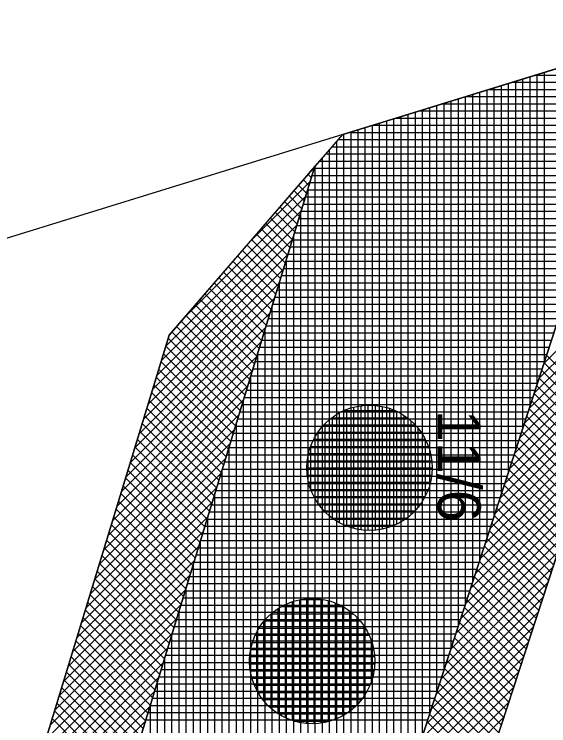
# Model space of a CAD drawing. Extents: x -565346 to -564154, y -1097386 to -1095620.
# Drawn here: x -564238.99 to -564224.07, y -1096458.56 to -1096438.69 of the extents above; entities that cross this region are included whole.
import ezdxf

# ---------------------------------------------------------------- set-up
doc = ezdxf.new("R2010")
doc.units = 0
for name, color, linetype in [('Vrstva 1', 7, 'Continuous'), ('Vrstva 13', 7, 'Continuous'), ('Vrstva 40', 7, 'Continuous'), ('Vrstva 41', 7, 'Continuous'), ('Vrstva 42', 7, 'Continuous'), ('Vrstva 43', 7, 'Continuous'), ('Vrstva 44', 7, 'Continuous')]:
    doc.layers.add(name, color=color, linetype=linetype)

msp = doc.modelspace()

# ---------------------------------------------------------------- linework, layer by layer
at = {"layer": 'Vrstva 1'}
for p, q in [((-564229.82, -1096442.05), (-564218.92, -1096438.69)), ((-564229.82, -1096442.05), (-564251.25, -1096448.66)), ((-564234.67, -1096447.65), (-564229.82, -1096442.05)), ((-564259.14, -1096527.84), (-564234.67, -1096447.65))]:
    msp.add_line(p, q, dxfattribs=at)
at = {"layer": 'Vrstva 13'}
msp.add_line((-564218.92, -1096438.69), (-564226.29, -1096461.3), dxfattribs=at)
at = {"layer": 'Vrstva 41'}
for points in [[(-564230.6, -1096442.93), (-564234.67, -1096447.65), (-564259.14, -1096527.84), (-564264.72, -1096575.85), (-564272.07, -1096706.16), (-564269.623, -1096706.334), (-564262.228, -1096576.061), (-564256.683, -1096528.354)], [(-564221.399, -1096446.296), (-564223.301, -1096445.676), (-564228.215, -1096460.758), (-564240.675, -1096505.018), (-564249.271, -1096529.938), (-564254.757, -1096576.767), (-564262.137, -1096706.758), (-564260.141, -1096706.872), (-564252.76, -1096576.88), (-564247.38, -1096530.59), (-564238.75, -1096505.56), (-564226.29, -1096461.3)]]:
    msp.add_lwpolyline(points, close=True, dxfattribs=at)
at = {"layer": 'Vrstva 42'}
for p, q in [((-564230.608, -1096442.955), (-564230.71, -1096443.057)), ((-564230.664, -1096443.004), (-564230.632, -1096443.036)), ((-564230.926, -1096443.308), (-564230.765, -1096443.469)), ((-564230.795, -1096443.156), (-564230.699, -1096443.253)), ((-564230.732, -1096443.362), (-564232.481, -1096445.111)), ((-564231.057, -1096443.46), (-564230.831, -1096443.686)), ((-564231.188, -1096443.612), (-564230.897, -1096443.903)), ((-564230.856, -1096443.77), (-564234.252, -1096447.165)), ((-564231.45, -1096443.916), (-564231.029, -1096444.336)), ((-564231.319, -1096443.764), (-564230.963, -1096444.12)), ((-564231.581, -1096444.068), (-564231.096, -1096444.553)), ((-564230.981, -1096444.177), (-564234.765, -1096447.961)), ((-564231.712, -1096444.219), (-564231.162, -1096444.77)), ((-564231.843, -1096444.371), (-564231.228, -1096444.986)), ((-564231.105, -1096444.584), (-564234.889, -1096448.368)), ((-564232.105, -1096444.675), (-564231.36, -1096445.42)), ((-564231.974, -1096444.523), (-564231.294, -1096445.203)), ((-564232.236, -1096444.827), (-564231.426, -1096445.636)), ((-564231.229, -1096444.991), (-564235.013, -1096448.775)), ((-564232.367, -1096444.979), (-564231.492, -1096445.853)), ((-564232.629, -1096445.283), (-564231.625, -1096446.286)), ((-564232.498, -1096445.131), (-564231.559, -1096446.07)), ((-564231.354, -1096445.398), (-564235.138, -1096449.182)), ((-564232.76, -1096445.434), (-564231.691, -1096446.503)), ((-564232.891, -1096445.586), (-564231.757, -1096446.72)), ((-564231.478, -1096445.805), (-564235.262, -1096449.589)), ((-564233.152, -1096445.89), (-564231.889, -1096447.153)), ((-564233.021, -1096445.738), (-564231.823, -1096446.936)), ((-564233.283, -1096446.042), (-564231.956, -1096447.37)), ((-564231.602, -1096446.213), (-564235.386, -1096449.996)), ((-564233.414, -1096446.194), (-564232.022, -1096447.586)), ((-564221.471, -1096446.273), (-564224.474, -1096449.275)), ((-564221.685, -1096446.203), (-564224.337, -1096448.855)), ((-564221.898, -1096446.134), (-564224.2, -1096448.436)), ((-564233.676, -1096446.498), (-564232.154, -1096448.02)), ((-564233.545, -1096446.346), (-564232.088, -1096447.803)), ((-564231.727, -1096446.62), (-564235.51, -1096450.403)), ((-564233.807, -1096446.649), (-564232.22, -1096448.236)), ((-564221.49, -1096446.574), (-564224.61, -1096449.694)), ((-564233.938, -1096446.801), (-564232.286, -1096448.453)), ((-564231.851, -1096447.027), (-564235.634, -1096450.81)), ((-564234.069, -1096446.953), (-564232.353, -1096448.67)), ((-564221.627, -1096446.994), (-564224.747, -1096450.114)), ((-564234.331, -1096447.257), (-564232.485, -1096449.103)), ((-564234.2, -1096447.105), (-564232.419, -1096448.887)), ((-564231.975, -1096447.434), (-564235.759, -1096451.217)), ((-564234.462, -1096447.409), (-564232.551, -1096449.32)), ((-564221.763, -1096447.413), (-564224.884, -1096450.533)), ((-564234.593, -1096447.561), (-564232.617, -1096449.537)), ((-564232.1, -1096447.841), (-564235.883, -1096451.624)), ((-564234.697, -1096447.739), (-564232.683, -1096449.753)), ((-564221.9, -1096447.833), (-564225.02, -1096450.953)), ((-564234.763, -1096447.956), (-564232.75, -1096449.97)), ((-564232.224, -1096448.248), (-564236.007, -1096452.031)), ((-564234.83, -1096448.173), (-564232.816, -1096450.187)), ((-564222.037, -1096448.252), (-564225.157, -1096451.372)), ((-564224.127, -1096448.213), (-564222.541, -1096449.799)), ((-564234.896, -1096448.389), (-564232.882, -1096450.403)), ((-564224.197, -1096448.426), (-564222.611, -1096450.012)), ((-564232.348, -1096448.656), (-564236.131, -1096452.439)), ((-564234.962, -1096448.606), (-564232.948, -1096450.62)), ((-564222.174, -1096448.672), (-564225.294, -1096451.792)), ((-564224.266, -1096448.639), (-564222.68, -1096450.226)), ((-564235.028, -1096448.823), (-564233.014, -1096450.837)), ((-564224.336, -1096448.853), (-564222.75, -1096450.439)), ((-564232.473, -1096449.063), (-564236.255, -1096452.846)), ((-564235.094, -1096449.04), (-564233.08, -1096451.053)), ((-564224.405, -1096449.066), (-564222.819, -1096450.652)), ((-564235.16, -1096449.256), (-564233.147, -1096451.27)), ((-564222.311, -1096449.092), (-564225.43, -1096452.211)), ((-564224.475, -1096449.279), (-564222.889, -1096450.865)), ((-564232.597, -1096449.47), (-564236.38, -1096453.253)), ((-564235.226, -1096449.473), (-564233.213, -1096451.487)), ((-564222.447, -1096449.511), (-564225.567, -1096452.631)), ((-564224.544, -1096449.493), (-564222.958, -1096451.079)), ((-564232.721, -1096449.877), (-564236.504, -1096453.66)), ((-564235.292, -1096449.69), (-564233.279, -1096451.703)), ((-564224.614, -1096449.706), (-564223.028, -1096451.292)), ((-564235.359, -1096449.906), (-564233.345, -1096451.92)), ((-564222.584, -1096449.931), (-564225.704, -1096453.051)), ((-564224.684, -1096449.919), (-564223.097, -1096451.505)), ((-564235.425, -1096450.123), (-564233.411, -1096452.137)), ((-564224.753, -1096450.133), (-564223.167, -1096451.719)), ((-564232.845, -1096450.284), (-564236.628, -1096454.067)), ((-564235.491, -1096450.34), (-564233.477, -1096452.353)), ((-564222.721, -1096450.351), (-564225.84, -1096453.47)), ((-564224.823, -1096450.346), (-564223.236, -1096451.932)), ((-564235.557, -1096450.557), (-564233.543, -1096452.57)), ((-564224.892, -1096450.559), (-564223.306, -1096452.145)), ((-564232.97, -1096450.691), (-564236.752, -1096454.474)), ((-564235.623, -1096450.773), (-564233.61, -1096452.787)), ((-564222.858, -1096450.77), (-564225.977, -1096453.89)), ((-564224.962, -1096450.773), (-564223.375, -1096452.359)), ((-564235.689, -1096450.99), (-564233.676, -1096453.003)), ((-564225.031, -1096450.986), (-564223.445, -1096452.572)), ((-564233.094, -1096451.098), (-564236.876, -1096454.881)), ((-564235.755, -1096451.207), (-564233.742, -1096453.22)), ((-564222.994, -1096451.19), (-564226.114, -1096454.309)), ((-564225.101, -1096451.199), (-564223.515, -1096452.785)), ((-564235.821, -1096451.423), (-564233.808, -1096453.437)), ((-564225.17, -1096451.413), (-564223.584, -1096452.999)), ((-564233.218, -1096451.506), (-564237.001, -1096455.288)), ((-564235.888, -1096451.64), (-564233.874, -1096453.654)), ((-564223.131, -1096451.609), (-564226.251, -1096454.729)), ((-564225.24, -1096451.626), (-564223.654, -1096453.212)), ((-564235.954, -1096451.857), (-564233.94, -1096453.87)), ((-564225.309, -1096451.839), (-564223.723, -1096453.425)), ((-564233.343, -1096451.913), (-564237.125, -1096455.695)), ((-564223.268, -1096452.029), (-564226.387, -1096455.148)), ((-564225.379, -1096452.053), (-564223.793, -1096453.638)), ((-564236.02, -1096452.074), (-564234.007, -1096454.087)), ((-564233.467, -1096452.32), (-564237.249, -1096456.102)), ((-564236.086, -1096452.29), (-564234.073, -1096454.304)), ((-564223.405, -1096452.449), (-564226.524, -1096455.568)), ((-564225.448, -1096452.266), (-564223.862, -1096453.852)), ((-564236.152, -1096452.507), (-564234.139, -1096454.52)), ((-564225.518, -1096452.479), (-564223.932, -1096454.065)), ((-564233.591, -1096452.727), (-564237.373, -1096456.509)), ((-564236.218, -1096452.724), (-564234.205, -1096454.737)), ((-564225.587, -1096452.693), (-564224.001, -1096454.278)), ((-564236.284, -1096452.94), (-564234.271, -1096454.954)), ((-564223.542, -1096452.868), (-564226.661, -1096455.987)), ((-564225.657, -1096452.906), (-564224.071, -1096454.492)), ((-564233.716, -1096453.134), (-564237.498, -1096456.916)), ((-564236.351, -1096453.157), (-564234.337, -1096455.17)), ((-564225.726, -1096453.119), (-564224.14, -1096454.705)), ((-564236.417, -1096453.374), (-564234.404, -1096455.387)), ((-564223.678, -1096453.288), (-564226.797, -1096456.407)), ((-564225.796, -1096453.333), (-564224.21, -1096454.918)), ((-564233.84, -1096453.541), (-564237.622, -1096457.323)), ((-564236.483, -1096453.591), (-564234.47, -1096455.604)), ((-564225.865, -1096453.546), (-564224.279, -1096455.132)), ((-564236.549, -1096453.807), (-564234.536, -1096455.82)), ((-564223.815, -1096453.708), (-564226.934, -1096456.826)), ((-564225.935, -1096453.759), (-564224.349, -1096455.345)), ((-564233.964, -1096453.949), (-564237.746, -1096457.73)), ((-564236.615, -1096454.024), (-564234.602, -1096456.037)), ((-564226.004, -1096453.973), (-564224.418, -1096455.558)), ((-564236.681, -1096454.241), (-564234.668, -1096456.254)), ((-564223.952, -1096454.127), (-564227.071, -1096457.246)), ((-564226.074, -1096454.186), (-564224.488, -1096455.772)), ((-564234.089, -1096454.356), (-564237.87, -1096458.137)), ((-564226.143, -1096454.399), (-564224.557, -1096455.985)), ((-564236.747, -1096454.457), (-564234.734, -1096456.47)), ((-564224.089, -1096454.547), (-564227.207, -1096457.665)), ((-564226.213, -1096454.613), (-564224.627, -1096456.198)), ((-564234.213, -1096454.763), (-564237.994, -1096458.544)), ((-564236.813, -1096454.674), (-564234.801, -1096456.687)), ((-564226.282, -1096454.826), (-564224.697, -1096456.412)), ((-564236.88, -1096454.891), (-564234.867, -1096456.904)), ((-564224.225, -1096454.966), (-564227.344, -1096458.085)), ((-564226.352, -1096455.039), (-564224.766, -1096456.625)), ((-564234.337, -1096455.17), (-564238.119, -1096458.951)), ((-564236.946, -1096455.108), (-564234.933, -1096457.12)), ((-564237.012, -1096455.324), (-564234.999, -1096457.337)), ((-564224.362, -1096455.386), (-564227.481, -1096458.505)), ((-564226.421, -1096455.253), (-564224.836, -1096456.838)), ((-564234.462, -1096455.577), (-564238.243, -1096459.358)), ((-564237.078, -1096455.541), (-564235.065, -1096457.554)), ((-564226.491, -1096455.466), (-564224.905, -1096457.051)), ((-564237.144, -1096455.758), (-564235.131, -1096457.77)), ((-564224.499, -1096455.806), (-564227.617, -1096458.924)), ((-564226.56, -1096455.679), (-564224.975, -1096457.265)), ((-564234.586, -1096455.984), (-564238.367, -1096459.766)), ((-564237.21, -1096455.974), (-564235.197, -1096457.987)), ((-564226.63, -1096455.893), (-564225.044, -1096457.478)), ((-564237.276, -1096456.191), (-564235.264, -1096458.204)), ((-564224.636, -1096456.225), (-564227.754, -1096459.344)), ((-564226.699, -1096456.106), (-564225.114, -1096457.691)), ((-564234.71, -1096456.392), (-564238.491, -1096460.173)), ((-564237.342, -1096456.408), (-564235.33, -1096458.421)), ((-564226.769, -1096456.319), (-564225.183, -1096457.905)), ((-564237.409, -1096456.625), (-564235.396, -1096458.637)), ((-564226.838, -1096456.533), (-564225.253, -1096458.118)), ((-564234.835, -1096456.799), (-564238.615, -1096460.58)), ((-564224.773, -1096456.645), (-564227.891, -1096459.763)), ((-564226.908, -1096456.746), (-564225.322, -1096458.331)), ((-564237.475, -1096456.841), (-564235.462, -1096458.854)), ((-564226.977, -1096456.959), (-564225.392, -1096458.545)), ((-564234.959, -1096457.206), (-564238.74, -1096460.987)), ((-564237.541, -1096457.058), (-564235.528, -1096459.071)), ((-564224.909, -1096457.065), (-564228.028, -1096460.183)), ((-564227.047, -1096457.173), (-564225.461, -1096458.758)), ((-564237.607, -1096457.275), (-564235.594, -1096459.287)), ((-564227.116, -1096457.386), (-564225.531, -1096458.971)), ((-564235.083, -1096457.613), (-564238.864, -1096461.394)), ((-564237.673, -1096457.491), (-564235.661, -1096459.504)), ((-564225.046, -1096457.484), (-564228.164, -1096460.602)), ((-564227.186, -1096457.599), (-564225.6, -1096459.185)), ((-564237.739, -1096457.708), (-564235.727, -1096459.721)), ((-564227.255, -1096457.813), (-564225.67, -1096459.398)), ((-564235.208, -1096458.02), (-564238.988, -1096461.801)), ((-564237.805, -1096457.925), (-564235.793, -1096459.937)), ((-564225.183, -1096457.904), (-564228.285, -1096461.005)), ((-564227.325, -1096458.026), (-564225.74, -1096459.611)), ((-564237.872, -1096458.142), (-564235.859, -1096460.154)), ((-564237.938, -1096458.358), (-564235.925, -1096460.371)), ((-564225.32, -1096458.323), (-564228.395, -1096461.399)), ((-564227.394, -1096458.239), (-564225.809, -1096459.825)), ((-564235.332, -1096458.427), (-564239.112, -1096462.208)), ((-564227.464, -1096458.453), (-564225.879, -1096460.038))]:
    msp.add_line(p, q, dxfattribs=at)
at = {"layer": 'Vrstva 43'}
for p, q in [((-564224.19, -1096448.405), (-564224.19, -1096440.315)), ((-564224.79, -1096450.246), (-564224.79, -1096440.499)), ((-564224.59, -1096449.632), (-564224.59, -1096440.438)), ((-564224.435, -1096440.39), (-564219.474, -1096440.39)), ((-564224.39, -1096449.018), (-564224.39, -1096440.376)), ((-564225.39, -1096452.088), (-564225.39, -1096440.684)), ((-564225.19, -1096451.474), (-564225.19, -1096440.623)), ((-564225.084, -1096440.59), (-564219.539, -1096440.59)), ((-564224.99, -1096450.86), (-564224.99, -1096440.561)), ((-564226.19, -1096454.543), (-564226.19, -1096440.931)), ((-564225.99, -1096453.929), (-564225.99, -1096440.869)), ((-564225.79, -1096453.315), (-564225.79, -1096440.808)), ((-564225.732, -1096440.79), (-564219.605, -1096440.79)), ((-564225.59, -1096452.701), (-564225.59, -1096440.746)), ((-564226.79, -1096456.384), (-564226.79, -1096441.116)), ((-564226.59, -1096455.771), (-564226.59, -1096441.054)), ((-564226.39, -1096455.157), (-564226.39, -1096440.993)), ((-564226.381, -1096440.99), (-564219.67, -1096440.99)), ((-564227.39, -1096458.226), (-564227.39, -1096441.301)), ((-564227.19, -1096457.612), (-564227.19, -1096441.239)), ((-564227.03, -1096441.19), (-564219.735, -1096441.19)), ((-564226.99, -1096456.998), (-564226.99, -1096441.178)), ((-564227.99, -1096460.067), (-564227.99, -1096441.486)), ((-564227.79, -1096459.454), (-564227.79, -1096441.424)), ((-564227.679, -1096441.39), (-564219.8, -1096441.39)), ((-564227.59, -1096458.84), (-564227.59, -1096441.363)), ((-564228.79, -1096462.801), (-564228.79, -1096441.732)), ((-564228.59, -1096462.09), (-564228.59, -1096441.671)), ((-564228.39, -1096461.38), (-564228.39, -1096441.609)), ((-564228.328, -1096441.59), (-564219.865, -1096441.59)), ((-564228.19, -1096460.681), (-564228.19, -1096441.548)), ((-564229.39, -1096464.932), (-564229.39, -1096441.917)), ((-564229.19, -1096464.221), (-564229.19, -1096441.856)), ((-564228.99, -1096463.511), (-564228.99, -1096441.794)), ((-564228.977, -1096441.79), (-564219.93, -1096441.79)), ((-564229.79, -1096466.353), (-564229.79, -1096442.041)), ((-564229.625, -1096441.99), (-564219.996, -1096441.99)), ((-564229.59, -1096465.642), (-564229.59, -1096441.979)), ((-564229.99, -1096467.063), (-564229.99, -1096442.242)), ((-564229.944, -1096442.19), (-564220.061, -1096442.19)), ((-564230.19, -1096467.774), (-564230.19, -1096442.467)), ((-564230.121, -1096442.39), (-564220.126, -1096442.39)), ((-564230.39, -1096468.484), (-564230.39, -1096442.693)), ((-564230.299, -1096442.59), (-564220.191, -1096442.59)), ((-564230.59, -1096469.194), (-564230.59, -1096442.919)), ((-564230.476, -1096442.79), (-564220.256, -1096442.79)), ((-564230.618, -1096442.99), (-564220.322, -1096442.99)), ((-564230.679, -1096443.19), (-564220.387, -1096443.19)), ((-564230.74, -1096443.39), (-564220.452, -1096443.39)), ((-564230.802, -1096443.59), (-564220.517, -1096443.59)), ((-564230.79, -1096469.905), (-564230.79, -1096443.552)), ((-564230.863, -1096443.79), (-564220.582, -1096443.79)), ((-564230.924, -1096443.99), (-564220.648, -1096443.99)), ((-564230.99, -1096470.615), (-564230.99, -1096444.207)), ((-564230.985, -1096444.19), (-564220.713, -1096444.19)), ((-564231.046, -1096444.39), (-564220.778, -1096444.39)), ((-564231.107, -1096444.59), (-564220.843, -1096444.59)), ((-564231.19, -1096471.326), (-564231.19, -1096444.862)), ((-564231.168, -1096444.79), (-564220.908, -1096444.79)), ((-564231.229, -1096444.99), (-564220.974, -1096444.99)), ((-564231.29, -1096445.19), (-564221.039, -1096445.19)), ((-564231.351, -1096445.39), (-564221.104, -1096445.39)), ((-564231.412, -1096445.59), (-564221.169, -1096445.59)), ((-564231.39, -1096472.036), (-564231.39, -1096445.517)), ((-564231.473, -1096445.79), (-564223.338, -1096445.79)), ((-564231.534, -1096445.99), (-564223.403, -1096445.99)), ((-564231.595, -1096446.19), (-564223.468, -1096446.19)), ((-564231.59, -1096472.747), (-564231.59, -1096446.172)), ((-564231.656, -1096446.39), (-564223.534, -1096446.39)), ((-564231.718, -1096446.59), (-564223.599, -1096446.59)), ((-564231.79, -1096473.457), (-564231.79, -1096446.827)), ((-564231.779, -1096446.79), (-564223.664, -1096446.79)), ((-564231.84, -1096446.99), (-564223.729, -1096446.99)), ((-564231.901, -1096447.19), (-564223.794, -1096447.19)), ((-564231.99, -1096474.167), (-564231.99, -1096447.482)), ((-564231.962, -1096447.39), (-564223.859, -1096447.39)), ((-564232.023, -1096447.59), (-564223.925, -1096447.59)), ((-564232.084, -1096447.79), (-564223.99, -1096447.79)), ((-564232.145, -1096447.99), (-564224.055, -1096447.99)), ((-564232.206, -1096448.19), (-564224.12, -1096448.19)), ((-564232.19, -1096474.878), (-564232.19, -1096448.137)), ((-564232.267, -1096448.39), (-564224.185, -1096448.39)), ((-564232.328, -1096448.59), (-564224.25, -1096448.59)), ((-564232.39, -1096475.588), (-564232.39, -1096448.792)), ((-564232.389, -1096448.79), (-564224.316, -1096448.79)), ((-564232.45, -1096448.99), (-564224.381, -1096448.99)), ((-564232.511, -1096449.19), (-564224.446, -1096449.19)), ((-564232.59, -1096476.299), (-564232.59, -1096449.447)), ((-564232.572, -1096449.39), (-564224.511, -1096449.39)), ((-564232.634, -1096449.59), (-564224.576, -1096449.59)), ((-564232.695, -1096449.79), (-564224.641, -1096449.79)), ((-564232.756, -1096449.99), (-564224.707, -1096449.99)), ((-564232.817, -1096450.19), (-564224.772, -1096450.19)), ((-564232.79, -1096477.009), (-564232.79, -1096450.102)), ((-564232.878, -1096450.39), (-564224.837, -1096450.39)), ((-564232.939, -1096450.59), (-564224.902, -1096450.59)), ((-564233, -1096450.79), (-564224.967, -1096450.79)), ((-564232.99, -1096477.72), (-564232.99, -1096450.757)), ((-564233.061, -1096450.99), (-564225.032, -1096450.99)), ((-564233.122, -1096451.19), (-564225.098, -1096451.19)), ((-564233.19, -1096478.43), (-564233.19, -1096451.412)), ((-564233.183, -1096451.39), (-564225.163, -1096451.39)), ((-564233.244, -1096451.59), (-564225.228, -1096451.59)), ((-564233.305, -1096451.79), (-564225.293, -1096451.79)), ((-564233.366, -1096451.99), (-564225.358, -1096451.99)), ((-564233.427, -1096452.19), (-564225.423, -1096452.19)), ((-564233.39, -1096479.14), (-564233.39, -1096452.067)), ((-564233.488, -1096452.39), (-564225.489, -1096452.39)), ((-564233.55, -1096452.59), (-564225.554, -1096452.59)), ((-564233.611, -1096452.79), (-564225.619, -1096452.79)), ((-564233.59, -1096479.851), (-564233.59, -1096452.723)), ((-564233.672, -1096452.99), (-564225.684, -1096452.99)), ((-564233.733, -1096453.19), (-564225.749, -1096453.19)), ((-564233.794, -1096453.39), (-564225.814, -1096453.39)), ((-564233.79, -1096480.561), (-564233.79, -1096453.378)), ((-564233.855, -1096453.59), (-564225.88, -1096453.59)), ((-564233.916, -1096453.79), (-564225.945, -1096453.79)), ((-564233.99, -1096481.272), (-564233.99, -1096454.033)), ((-564233.977, -1096453.99), (-564226.01, -1096453.99)), ((-564234.038, -1096454.19), (-564226.075, -1096454.19)), ((-564234.099, -1096454.39), (-564226.14, -1096454.39)), ((-564234.16, -1096454.59), (-564226.205, -1096454.59)), ((-564234.221, -1096454.79), (-564226.271, -1096454.79)), ((-564234.19, -1096481.982), (-564234.19, -1096454.688)), ((-564234.282, -1096454.99), (-564226.336, -1096454.99)), ((-564234.343, -1096455.19), (-564226.401, -1096455.19)), ((-564234.404, -1096455.39), (-564226.466, -1096455.39)), ((-564234.39, -1096482.693), (-564234.39, -1096455.343)), ((-564234.466, -1096455.59), (-564226.531, -1096455.59)), ((-564234.527, -1096455.79), (-564226.596, -1096455.79)), ((-564234.59, -1096483.403), (-564234.59, -1096455.998)), ((-564234.588, -1096455.99), (-564226.661, -1096455.99)), ((-564234.649, -1096456.19), (-564226.727, -1096456.19)), ((-564234.71, -1096456.39), (-564226.792, -1096456.39)), ((-564234.771, -1096456.59), (-564226.857, -1096456.59)), ((-564234.832, -1096456.79), (-564226.922, -1096456.79)), ((-564234.79, -1096484.114), (-564234.79, -1096456.653)), ((-564234.893, -1096456.99), (-564226.987, -1096456.99)), ((-564234.954, -1096457.19), (-564227.052, -1096457.19)), ((-564235.015, -1096457.39), (-564227.118, -1096457.39)), ((-564234.99, -1096484.824), (-564234.99, -1096457.308)), ((-564235.076, -1096457.59), (-564227.183, -1096457.59)), ((-564235.137, -1096457.79), (-564227.248, -1096457.79)), ((-564235.198, -1096457.99), (-564227.313, -1096457.99)), ((-564235.19, -1096485.534), (-564235.19, -1096457.963)), ((-564235.259, -1096458.19), (-564227.378, -1096458.19)), ((-564235.32, -1096458.39), (-564227.443, -1096458.39))]:
    msp.add_line(p, q, dxfattribs=at)
msp.add_lwpolyline([(-564261.274, -1096726.84), (-564260.141, -1096706.872), (-564262.137, -1096706.758), (-564254.757, -1096576.767), (-564249.271, -1096529.938), (-564240.675, -1096505.018), (-564228.215, -1096460.758), (-564223.301, -1096445.676), (-564221.399, -1096446.296), (-564218.92, -1096438.69), (-564229.82, -1096442.05), (-564230.6, -1096442.93), (-564256.683, -1096528.354), (-564262.228, -1096576.061), (-564269.623, -1096706.334), (-564272.07, -1096706.16), (-564273.28, -1096725.96)], dxfattribs=at)
at = {"layer": 'Vrstva 44'}
for p, q in [((-564229.51, -1096453.048), (-564229.51, -1096449.661)), ((-564229.31, -1096453.087), (-564229.31, -1096449.622)), ((-564229.11, -1096453.103), (-564229.11, -1096449.606)), ((-564228.91, -1096453.095), (-564228.91, -1096449.613)), ((-564228.71, -1096453.064), (-564228.71, -1096449.643)), ((-564229.91, -1096452.89), (-564229.91, -1096449.819)), ((-564229.792, -1096449.76), (-564228.356, -1096449.76)), ((-564229.71, -1096452.984), (-564229.71, -1096449.724)), ((-564228.51, -1096453.009), (-564228.51, -1096449.699)), ((-564228.31, -1096452.928), (-564228.31, -1096449.782)), ((-564230.131, -1096449.96), (-564228.019, -1096449.96)), ((-564230.11, -1096452.762), (-564230.11, -1096449.945)), ((-564228.11, -1096452.812), (-564228.11, -1096449.894)), ((-564227.91, -1096452.66), (-564227.91, -1096450.05)), ((-564230.351, -1096450.16), (-564227.797, -1096450.16)), ((-564230.31, -1096452.591), (-564230.31, -1096450.118)), ((-564227.71, -1096452.447), (-564227.71, -1096450.26)), ((-564230.513, -1096450.36), (-564227.634, -1096450.36)), ((-564230.51, -1096452.354), (-564230.51, -1096450.356)), ((-564230.632, -1096450.56), (-564227.517, -1096450.56)), ((-564227.51, -1096452.137), (-564227.51, -1096450.574)), ((-564230.72, -1096450.76), (-564227.43, -1096450.76)), ((-564230.71, -1096451.971), (-564230.71, -1096450.736)), ((-564230.778, -1096450.96), (-564227.37, -1096450.96)), ((-564230.811, -1096451.16), (-564227.336, -1096451.16)), ((-564230.822, -1096451.36), (-564227.326, -1096451.36)), ((-564230.811, -1096451.56), (-564227.338, -1096451.56)), ((-564230.776, -1096451.76), (-564227.374, -1096451.76)), ((-564230.714, -1096451.96), (-564227.433, -1096451.96)), ((-564230.625, -1096452.16), (-564227.523, -1096452.16)), ((-564230.506, -1096452.36), (-564227.644, -1096452.36)), ((-564230.34, -1096452.56), (-564227.808, -1096452.56)), ((-564230.113, -1096452.76), (-564228.033, -1096452.76)), ((-564229.766, -1096452.96), (-564228.384, -1096452.96)), ((-564231.02, -1096458.468), (-564231.02, -1096455.04)), ((-564230.972, -1096455.03), (-564230.385, -1096455.03)), ((-564230.82, -1096458.496), (-564230.82, -1096455.01)), ((-564230.62, -1096458.501), (-564230.62, -1096455.006)), ((-564230.42, -1096458.484), (-564230.42, -1096455.024)), ((-564231.53, -1096455.23), (-564229.817, -1096455.23)), ((-564231.42, -1096458.335), (-564231.42, -1096455.173)), ((-564231.22, -1096458.415), (-564231.22, -1096455.093)), ((-564230.22, -1096458.444), (-564230.22, -1096455.066)), ((-564230.02, -1096458.375), (-564230.02, -1096455.132)), ((-564229.82, -1096458.279), (-564229.82, -1096455.228)), ((-564231.82, -1096458.074), (-564231.82, -1096455.434)), ((-564231.816, -1096455.43), (-564229.532, -1096455.43)), ((-564231.62, -1096458.226), (-564231.62, -1096455.283)), ((-564229.62, -1096458.15), (-564229.62, -1096455.36)), ((-564232.02, -1096457.871), (-564232.02, -1096455.638)), ((-564232.013, -1096455.63), (-564229.333, -1096455.63)), ((-564229.42, -1096457.972), (-564229.42, -1096455.535)), ((-564232.159, -1096455.83), (-564229.19, -1096455.83)), ((-564229.22, -1096457.724), (-564229.22, -1096455.782)), ((-564232.267, -1096456.03), (-564229.082, -1096456.03)), ((-564232.22, -1096457.57), (-564232.22, -1096455.938)), ((-564232.342, -1096456.23), (-564229.005, -1096456.23)), ((-564229.02, -1096457.32), (-564229.02, -1096456.186)), ((-564232.392, -1096456.43), (-564228.956, -1096456.43)), ((-564232.419, -1096456.63), (-564228.931, -1096456.63)), ((-564232.422, -1096456.83), (-564228.927, -1096456.83)), ((-564232.42, -1096456.856), (-564232.42, -1096456.643)), ((-564232.401, -1096457.03), (-564228.947, -1096457.03)), ((-564232.356, -1096457.23), (-564228.991, -1096457.23)), ((-564232.287, -1096457.43), (-564229.062, -1096457.43)), ((-564232.189, -1096457.63), (-564229.161, -1096457.63)), ((-564232.052, -1096457.83), (-564229.296, -1096457.83)), ((-564231.871, -1096458.03), (-564229.478, -1096458.03)), ((-564231.613, -1096458.23), (-564229.736, -1096458.23)), ((-564231.177, -1096458.43), (-564230.177, -1096458.43))]:
    msp.add_line(p, q, dxfattribs=at)
for centre in [(-564229.074, -1096451.354), (-564230.674, -1096456.754)]:
    msp.add_circle(centre, 1.75, dxfattribs=at)

# ---------------------------------------------------------------- texts
at = {"layer": 'Vrstva 40'}
msp.add_text('11/6', height=1.2, rotation=270, dxfattribs=at).set_placement((-564227.17, -1096449.74))

doc.saveas('drawing.dxf')
